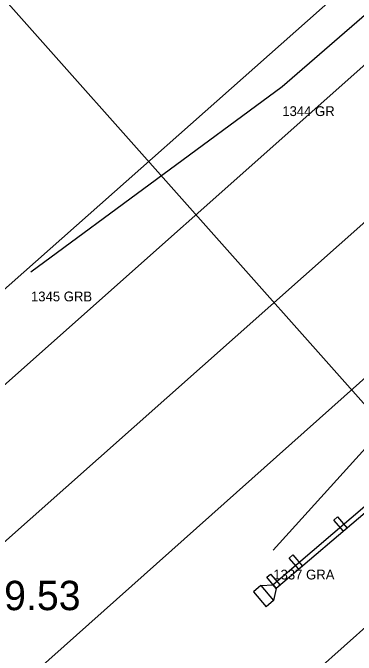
# Model space of a CAD drawing. Extents: x 49683 to 58852, y 49525 to 54803.
# Drawn here: x 53372.4 to 53407.5, y 51406.6 to 51472.3 of the extents above; entities that cross this region are included whole.
import ezdxf

# ---------------------------------------------------------------- set-up
doc = ezdxf.new("R2010")
doc.units = 0
for name, color, linetype in [('Level 1', 7, 'Continuous'), ('Level 11', 7, 'Continuous'), ('Level 20', 7, 'Continuous'), ('Level 27', 7, 'Continuous'), ('Level 3', 7, 'Continuous'), ('Level 32', 7, 'Continuous'), ('Level 50', 7, 'Continuous'), ('Level 57', 7, 'Continuous'), ('Level 63', 7, 'Continuous'), ('Level 7', 7, 'Continuous')]:
    doc.layers.add(name, color=color, linetype=linetype)

msp = doc.modelspace()

# ---------------------------------------------------------------- linework, layer by layer
at = {"layer": 'Level 1'}
msp.add_line((52544.807, 50683.302), (55534.583, 53340.862), dxfattribs=at)
at = {"layer": 'Level 11'}
msp.add_line((53157.705, 51254.454), (53424.495, 51490.929), dxfattribs=at)
at = {"layer": 'Level 20'}
msp.add_line((52704.846, 50784.08), (53476.257, 51469.774), dxfattribs=at)
at = {"layer": 'Level 27'}
for p, q in [((53437.052, 51446.298), (53399.017, 51413.828)), ((53437.377, 51445.918), (53399.342, 51413.448)), ((53397.77, 51413.749), (53397.009, 51413.1)), ((53397.77, 51413.749), (53399.017, 51413.828)), ((53397.77, 51413.749), (53399.069, 51412.228)), ((53399.017, 51413.828), (53399.342, 51413.448)), ((53397.009, 51413.1), (53398.308, 51411.579)), ((53399.342, 51413.448), (53399.069, 51412.228)), ((53399.069, 51412.228), (53398.308, 51411.579))]:
    msp.add_line(p, q, dxfattribs=at)
for points in [[(53406.575, 51419.622), (53406.195, 51419.298), (53405.221, 51420.439), (53405.602, 51420.763)], [(53402.012, 51415.726), (53401.631, 51415.402), (53400.658, 51416.543), (53401.038, 51416.868)], [(53399.723, 51413.772), (53399.342, 51413.448), (53398.369, 51414.589), (53398.749, 51414.913)]]:
    msp.add_lwpolyline(points, close=True, dxfattribs=at)
at = {"layer": 'Level 3'}
for p, q in [((53162.497, 51248.316), (53434.092, 51489.844)), ((53179.352, 51230.724), (53449.718, 51471.806))]:
    msp.add_line(p, q, dxfattribs=at)
at = {"layer": 'Level 50'}
msp.add_line((53349.287, 51498.735), (53508.734, 51319.357), dxfattribs=at)
at = {"layer": 'Level 63'}
msp.add_line((52716.814, 50794.718), (53451.1, 51447.413), dxfattribs=at)
at = {"layer": 'Level 7'}
for p, q in [((53431.716, 51492.319), (53399.953, 51464.721)), ((53399.953, 51464.721), (53374.288, 51445.784)), ((53399.036, 51417.365), (53424.8, 51445.953))]:
    msp.add_line(p, q, dxfattribs=at)

# ---------------------------------------------------------------- texts
at = {"layer": 'Level 32'}
msp.add_text('269.53', height=3, dxfattribs=at).set_placement((53367.084, 51411.23))
at = {"layer": 'Level 57'}
for s, p in [('1344 GR', (53399.953, 51461.721)), ('1345 GRB', (53374.288, 51442.784)), ('1337 GRA', (53399.036, 51414.365))]:
    msp.add_text(s, height=1, dxfattribs=at).set_placement(p)

doc.saveas('drawing.dxf')
